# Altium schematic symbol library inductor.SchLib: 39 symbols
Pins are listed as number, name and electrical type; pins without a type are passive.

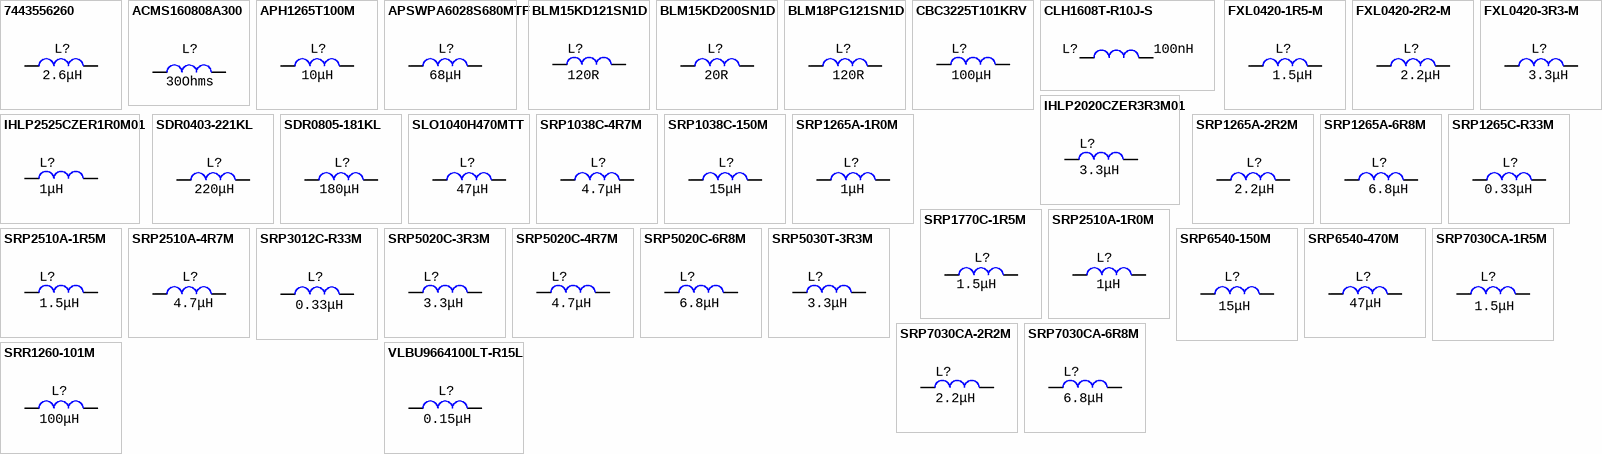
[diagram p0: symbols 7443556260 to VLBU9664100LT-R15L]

## 7443556260
designator L?  value 2.6μH  (hidden comment: 7443556260)
2.6 uH, 31.5A, ±20%, 1.58 mOhms, -40...+125°C; Manufacturer: Wurth; Manufacturer: Wurth Electronics
footprint IND: 7443556260 (Wurth)
pins: 1, 2

## ACMS160808A300
designator L?  value 30Ohms  (hidden comment: ACMS160808A300)
30 Ohms, Ferrite Bead, ±25%, 40 mOhms, 3A, 0603, -55...+125°C; Manufacturer: Max-Echo
footprint IND: 0603
pins: 1, 2

## APH1265T100M
designator L?  value 10μH  (hidden comment: APH1265T100M)
10 uH, 9.4A, ±20%, 22 mOhms, -40...+125°C; Manufacturer: APV
footprint IND: SRP1265A
pins: 1, 2

## APSWPA6028S680MTF
designator L?  value 68μH  (hidden comment: APSWPA6028S680MTF)
68 uH, 0.8A, ±20%, 468 mOhms, -40...+125°C; Manufacturer: APV
footprint IND: 6028
pins: 1, 2

## BLM15KD121SN1D
designator L?  value 120R  (hidden comment: BLM15KD121SN1D)
120R, Ferrite Bead, 1.5A, 70 mOhms, 0402, -55...+125°C; Manufacturer: Murata
footprint IND: 0402
pins: 1, 2

## BLM15KD200SN1D
designator L?  value 20R  (hidden comment: BLM15KD200SN1D)
20R, Ferrite Bead, 3.8A, 11 mOhms, 0402, -55...+125°C; Manufacturer: Murata
footprint IND: 0402
pins: 1, 2

## BLM18PG121SN1D
designator L?  value 120R  (hidden comment: BLM18PG121SN1D)
120R, Ferrite Bead, 2A, 50 mOhms, 0603, -55...+125°C; Manufacturer: Murata
footprint IND: 0603
pins: 1, 2

## CBC3225T101KRV
designator L?  value 100μH  (hidden comment: CBC3225T101KRV)
100 uH, 0.22A, ±10%, 1.82 Ohms, case 3225, -40...+125°C; Manufacturer: Taiyo Yuden
footprint IND: 3225 (1210)
pins: 1, 2

## CLH1608T-R10J-S
designator L?  value 100nH  (hidden comment: CLH1608T-R10J-S)
100 nH ±5%, 1.2Ohms, 0.3A, 0603, -55...+125°C; Manufacturer: Chilisin
footprint IND: 0603
pins: 1, 2

## FXL0420-1R5-M
designator L?  value 1.5μH  (hidden comment: FXL0420-1R5-M)
1.5 uH, 5A, ±20%, 11.5 mOhms, -40...+125°C; Manufacturer: Cjiang
footprint IND: SRP4020
pins: 1, 2

## FXL0420-2R2-M
designator L?  value 2.2μH  (hidden comment: FXL0420-2R2-M)
2.2 uH, 4.5A, ±20%, 58 mOhms, -40...+125°C; Manufacturer: Cjiang
footprint IND: SRP4020
pins: 1, 2

## FXL0420-3R3-M
designator L?  value 3.3μH  (hidden comment: FXL0420-3R3-M)
3.3 uH, 3.3A, ±20%, 87 mOhms, -40...+125°C; Manufacturer: Cjiang
footprint IND: SRP4020
pins: 1, 2

## IHLP2020CZER3R3M01
designator L?  value 3.3μH  (hidden comment: IHLP2020CZER3R3M01)
3.3 uH, 5A, ±20%, 55 mOhms, -55...+125°C; Manufacturer: Vishay / Dale; Manufacturer: Vishay Dale
footprint IND: IHLP2020CZER3R3M01
pins: 1, 2

## IHLP2525CZER1R0M01
designator L?  value 1μH  (hidden comment: IHLP2525CZER1R0M01)
1 uH, 11A, ±20%, 10 mOhms, -55...+125°C; Manufacturer: Vishay / Dale; Manufacturer: Vishay Dale
footprint IND: IHLP2525CZ
pins: 1, 2

## SDR0403-221KL
designator L?  value 220μH  (hidden comment: SDR0403-221KL)
220 uH, 0.22A, ±20%, 4.4 Ohms, -40...+125°C; Manufacturer: Bourns
footprint IND: SDR0403
pins: 1, 2

## SDR0805-181KL
designator L?  value 180μH  (hidden comment: SDR0805-181KL)
180 uH, 0.51A, ±10%, 770 mOhms, -40...+125°C; Manufacturer: Bourns
footprint IND: SDR0805
pins: 1, 2

## SLO1040H470MTT
designator L?  value 47μH  (hidden comment: SLO1040H470MTT)
47 uH, 3A, ±20%, 145 mOhms, -40...+125°C; Manufacturer: Sunltech Tech
footprint IND: SRP1038C
pins: 1, 2

## SRP1038C-4R7M
designator L?  value 4.7μH  (hidden comment: SRP1038C-4R7M)
4.7 uH, 13A, ±20%, 15.5 mOhms, -40...+125°C; Manufacturer: Bourns
footprint IND: SRP1038C
pins: 1, 2

## SRP1038C-150M
designator L?  value 15μH  (hidden comment: SRP1038C-150M)
15 uH, 6.3A, ±20%, 45 mOhms, -40...+125°C; Manufacturer: Bourns
footprint IND: SRP1038C
pins: 1, 2

## SRP1265A-1R0M
designator L?  value 1μH  (hidden comment: SRP1265A-1R0M)
1 uH, 48A, ±20%, 2.3 mOhms, -40...+125°C; Manufacturer: Bourns
footprint IND: SRP1265A
pins: 1, 2

## SRP1265A-2R2M
designator L?  value 2.2μH  (hidden comment: SRP1265A-2R2M)
2.2 uH, 37A, ±20%, 4.2 mOhms, -40...+125°C; Manufacturer: Bourns
footprint IND: SRP1265A
pins: 1, 2

## SRP1265A-6R8M
designator L?  value 6.8μH  (hidden comment: SRP1265A-6R8M)
6.8 uH, 18A, ±20%, 11.5 mOhms, -40...+125°C; Manufacturer: Bourns
footprint IND: SRP1265A
pins: 1, 2

## SRP1265C-R33M
designator L?  value 0.33μH  (hidden comment: SRP1265C-R33M)
0.33 uH, 70A, ±20%, 0.8 mOhms, -40...+125°C; Manufacturer: Bourns
footprint IND: SRP1265A
pins: 1, 2

## SRP1770C-1R5M
designator L?  value 1.5μH  (hidden comment: SRP1770C-1R5M)
1.5 uH, 55A, ±20%, 46 mOhms, -40...+125°C; Manufacturer: Bourns
footprint IND: SRP1770C
pins: 1, 2

## SRP2510A-1R0M
designator L?  value 1μH  (hidden comment: SRP2510A-1R0M)
1 uH, 3A, ±20%, 54 mOhms, -40...+125°C; Manufacturer: Bourns
footprint IND: SRP2510A
pins: 1, 2

## SRP2510A-1R5M
designator L?  value 1.5μH  (hidden comment: SRP2510A-1R5M)
1.5 uH, 2.5A, ±20%, 91 mOhms, -40...+125°C; Manufacturer: Bourns
footprint IND: SRP2510A
pins: 1, 2

## SRP2510A-4R7M
designator L?  value 4.7μH  (hidden comment: SRP2510A-4R7M)
4.7 uH, 1.36A, ±20%, 262 mOhms, -40...+125°C; Manufacturer: Bourns
footprint IND: SRP2510A
pins: 1, 2

## SRP3012C-R33M
designator L?  value 0.33μH  (hidden comment: SRP3012C-R33M)
0.33 uH, 7A, ±20%, 20 mOhms, -40...+125°C; Manufacturer: Bourns
footprint IND: SRP3012C
pins: 1, 2

## SRP5020C-3R3M
designator L?  value 3.3μH  (hidden comment: SRP5020C-3R3M)
3.3 uH, 4A, ±20%, 66 mOhms, -40...+125°C; Manufacturer: Bourns
footprint IND: SRP5020
pins: 1, 2

## SRP5020C-4R7M
designator L?  value 4.7μH  (hidden comment: SRP5020C-4R7M)
4.7 uH, 3.2A, ±20%, 109 mOhms, -40...+125°C; Manufacturer: Bourns
footprint IND: SRP5020
pins: 1, 2

## SRP5020C-6R8M
designator L?  value 6.8μH  (hidden comment: SRP5020C-6R8M)
6.8 uH, 2.8A, ±20%, 150 mOhms, -40...+125°C; Manufacturer: Bourns
footprint IND: SRP5020
pins: 1, 2

## SRP5030T-3R3M
designator L?  value 3.3μH  (hidden comment: SRP5030T-3R3M)
3.3 uH, 5A, ±20%, 38 mOhms, -40...+125°C; Manufacturer: Bourns
footprint IND: SRP5030T
pins: 1, 2

## SRP6540-150M
designator L?  value 15μH  (hidden comment: SRP6540-150M)
15 uH, 2.9A, ±20%, 121 mOhms, -40...+125°C; Manufacturer: Bourns
footprint IND: SRP6540
pins: 1, 2

## SRP6540-470M
designator L?  value 47μH  (hidden comment: SRP6540-470M)
47 uH, 1.6A, ±20%, 366 mOhms, -55...+125°C; Manufacturer: Bourns
footprint IND: SRP6540
pins: 1, 2

## SRP7030CA-1R5M
designator L?  value 1.5μH  (hidden comment: SRP7030CA-1R5M)
1.5 uH, 15.3A, ±20%, 8.25 mOhms, -40...+125°C; Manufacturer: Bourns
footprint IND: SRP7030CA
pins: 1, 2

## SRP7030CA-2R2M
designator L?  value 2.2μH  (hidden comment: SRP7030CA-2R2M)
2.2 uH, 13A, ±20%, 8.25 mOhms, -40...+125°C; Manufacturer: Bourns
footprint IND: SRP7030CA
pins: 1, 2

## SRP7030CA-6R8M
designator L?  value 6.8μH  (hidden comment: SRP7030CA-6R8M)
6.8 uH, 6.8A, ±20%, 42.5 mOhms, -40...+125°C; Manufacturer: Bourns
footprint IND: SRP7030CA
pins: 1, 2

## SRR1260-101M
designator L?  value 100μH  (hidden comment: SRR1260-101M)
100 uH, 1.7A, ±10%, 180 mOhms, -40...+125°C; Manufacturer: Bourns; Manufacturer Part Number: SRR1260-150M
footprint IND: SRR1260
pins: 1, 2

## VLBU9664100LT-R15L
designator L?  value 0.15μH  (hidden comment: VLBU9664100LT-R15L)
0.15 uH, 76A, ±15%, 0.125 mOhms, -40...+125°C; Manufacturer: TDK; Manufacturer Part Number: VLBU9664100LT-R10L
footprint IND: VLBU9664100LT
pins: 1, 2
